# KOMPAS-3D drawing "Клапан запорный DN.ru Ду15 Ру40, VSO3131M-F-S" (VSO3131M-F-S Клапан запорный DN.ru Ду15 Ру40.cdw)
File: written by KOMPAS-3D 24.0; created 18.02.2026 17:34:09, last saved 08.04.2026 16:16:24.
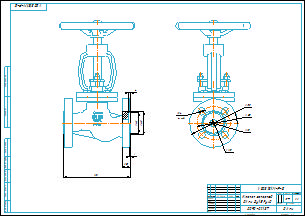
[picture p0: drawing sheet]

Document properties: Автор: R2D2; Форматы листов документа: A2; Полное имя файла: VSO3131M-F-S Клапан запорный DN.ru Ду15 Ру40.m3d; Масса: 3.77; Наименование: Клапан запорный DN.ru Ду15 Ру40; Количество листов документа: 1; Примечание: D090-02137

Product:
- Body: Тело 3  | qty 1
    Масса: 4.60476
- Part/product: Клапан запорный DN.ru Ду15 Ру40  | designation VSO3131M-F-S
    Масса: 3.77
    Раздел спецификации: Прочие изделия
    Примечание: D090-02137

Views: Вид 1, Местный разрез 1, Спереди
Referenced files in E:\Работа\Зайцев\VSO3131M-F-S Клапан запорный DN.ru Ду15-100 Ру40\DN15\: VSO3131M-F-S Клапан запорный DN.ru Ду15 Ру40.m3d
Referenced files in E:\Работа\Зайцев\VSO1121M-F-S Клапан запорный сальниковый DN.ru\DN15\: VSO1121M-F-S Клапан запорный DN.ru Ду15 Ру16.m3d
Referenced files in E:\Работа\Зайцев\Для компаса\: чертеж DN.ru А3.cdt
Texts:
  VSO3131M-F-S
  чертеж DN.ru А3.cdt
  Клапан запорный
  DN.ru Ду15 Ру40
  Клапан запорный DN.ru Ду15 Ру40
  VSO3131M-F-S Клапан запорный DN.ru Ду15 Ру40
Dimensions and other numbers on the sheet: 0; 3; 2; 4; 130; 16; 40; 45; 1:1; 1; 3,77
